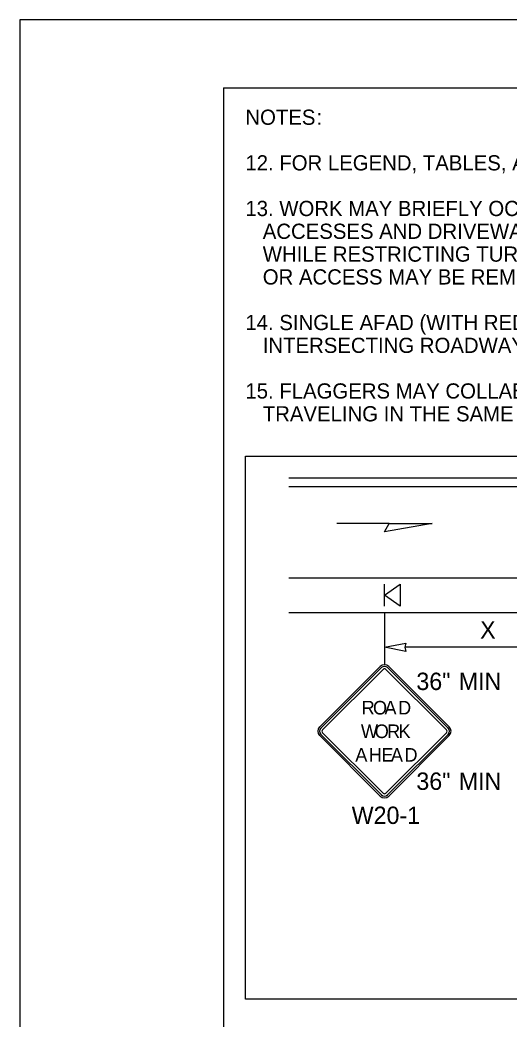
# Model space of a CAD drawing. Extents: x 99999.1 to 100095.7, y 99995 to 100010.7.
# Drawn here: x 100059.062 to 100061.313, y 100006.089 to 100010.687 of the extents above; entities that cross this region are included whole.
import ezdxf

# ---------------------------------------------------------------- set-up
doc = ezdxf.new("R2010")
doc.units = 0
for name, color, linetype in [('RD_ED_ShoulderPavedEdge', 7, 'Continuous'), ('RD_MK_LineDblYellowCenter', 7, 'Continuous'), ('RD_MK_LineEdgeWhite', 7, 'Continuous'), ('SH_GI_GeneralNotesBodyText', 7, 'Continuous'), ('SH_GI_PlotLimits', 7, 'Continuous'), ('SH_GI_SheetBorder', 7, 'Continuous'), ('TR_SN_ConstructionSigns', 7, 'Continuous'), ('TR_WZ_PortableSignMountBlk-Org', 7, 'Continuous'), ('TR_WZ_WorkZoneDetails', 7, 'Continuous'), ('TR_WZ_WorkZoneTextCurrent', 7, 'Continuous')]:
    doc.layers.add(name, color=color, linetype=linetype)

msp = doc.modelspace()

# ---------------------------------------------------------------- linework, layer by layer
at = {"layer": 'RD_ED_ShoulderPavedEdge'}
msp.add_line((100060.3, 100007.9602), (100064.9804, 100007.9602), dxfattribs=at)
at = {"layer": 'RD_MK_LineDblYellowCenter'}
for p, q in [((100060.3, 100008.5802), (100063.7402, 100008.5802)), ((100060.3, 100008.5402), (100063.7402, 100008.5402))]:
    msp.add_line(p, q, dxfattribs=at)
at = {"layer": 'RD_MK_LineEdgeWhite'}
msp.add_line((100060.3, 100008.1202), (100064.9804, 100008.1202), dxfattribs=at)
at = {"layer": 'SH_GI_PlotLimits'}
msp.add_lwpolyline([(100059.0625, 99999.6875), (100076.0625, 99999.6875), (100076.0625, 100010.6875), (100059.0625, 100010.6875)], close=True, dxfattribs=at)
at = {"layer": 'SH_GI_SheetBorder'}
for q in [(100060, 100000), (100075.75, 100010.375)]:
    msp.add_line((100060, 100010.375), q, dxfattribs=at)
at = {"layer": 'TR_SN_ConstructionSigns'}
for p, q in [((100060.7203, 100007.712), (100060.4419, 100007.4336)), ((100060.7258, 100007.7065), (100060.4474, 100007.428)), ((100060.4551, 100007.4203), (100060.7335, 100007.6987)), ((100060.7468, 100007.6987), (100061.0252, 100007.4203)), ((100061.0329, 100007.428), (100060.7545, 100007.7065)), ((100061.0385, 100007.4336), (100060.76, 100007.712)), ((100060.4474, 100007.3993), (100060.7258, 100007.1209)), ((100060.7335, 100007.1286), (100060.4551, 100007.4071)), ((100061.0252, 100007.4071), (100060.7468, 100007.1286)), ((100060.7545, 100007.1209), (100061.0329, 100007.3993)), ((100060.4419, 100007.3938), (100060.7203, 100007.1154)), ((100060.76, 100007.1154), (100061.0385, 100007.3938))]:
    msp.add_line(p, q, dxfattribs=at)
for centre, radius, start, end in [((100060.7402, 100007.6921), 0.0281, 45, 135), ((100060.7402, 100007.6921), 0.0203, 45, 135), ((100060.7402, 100007.6921), 0.00937, 45, 135), ((100060.4617, 100007.4137), 0.0281, 135, 225), ((100060.4617, 100007.4137), 0.0203, 135, 225), ((100060.4617, 100007.4137), 0.00937, 135, 225), ((100061.0186, 100007.4137), 0.00937, 315, 45), ((100061.0186, 100007.4137), 0.0203, 315, 45), ((100061.0186, 100007.4137), 0.0281, 315, 45), ((100060.7402, 100007.1353), 0.0203, 225, 315), ((100060.7402, 100007.1353), 0.00937, 225, 315), ((100060.7402, 100007.1353), 0.0281, 225, 315)]:
    msp.add_arc(centre, radius, start, end, dxfattribs=at)
at = {"layer": 'TR_WZ_PortableSignMountBlk-Org'}
msp.add_line((100060.7402, 100007.9902), (100060.7402, 100008.0902), dxfattribs=at)
msp.add_lwpolyline([(100060.7402, 100008.0401), (100060.812, 100008.0902), (100060.812, 100007.9902)], close=True, dxfattribs=at)
at = {"layer": 'TR_WZ_WorkZoneDetails'}
for p, q in [((100060.7624, 100008.3695), (100060.5213, 100008.3695)), ((100060.7402, 100007.9605), (100060.7402, 100007.7202)), ((100061.5964, 100007.8002), (100060.8339, 100007.8002))]:
    msp.add_line(p, q, dxfattribs=at)
for points in [[(100060.959, 100008.3695), (100060.7402, 100008.3309), (100060.7624, 100008.3695)], [(100060.7402, 100007.8002), (100060.8384, 100007.8195), (100060.8339, 100007.8002), (100060.8384, 100007.781)]]:
    msp.add_lwpolyline(points, close=True, dxfattribs=at)
at = {"layer": 'TR_WZ_WorkZoneTextCurrent'}
msp.add_lwpolyline([(100060.1, 100008.6802), (100065.15, 100008.6802), (100065.15, 100006.1804), (100060.1, 100006.1804)], close=True, dxfattribs=at)

# ---------------------------------------------------------------- texts
at = {"layer": 'SH_GI_GeneralNotesBodyText'}
for s, p in [('NOTES', (100060.1, 100010.205)), (':', (100060.4275, 100010.205)), ('12. FOR LEGEND, TABLES, AND ADDITIONAL NOTES: SEE TC430, SHEET 3.', (100060.1, 100009.995)), ('13. WORK MAY BRIEFLY OCCUR WITHIN LANE CLOSURE ACROSS INTERSECTING BUSINESS ', (100060.1, 100009.785)), ('ACCESSES AND DRIVEWAYS ONLY. ', (100060.18, 100009.68)), ('WHILE RESTRICTING TURNS FROM MAINLINE. CHANNELIZATION DEVICES DELINEATING APPROACH ', (100060.18, 100009.575)), ('OR ACCESS MAY BE REMOVED OR RELOCATED AS NEEDED.', (100060.18, 100009.47)), ('14. SINGLE AFAD (WITH RED FLAG/ RED GLOW CONE FLASHLIGHT) MAY BE ADDED TO THE ', (100060.1, 100009.26)), ('INTERSECTING ROADWAY APPROACH TO HELP GUIDE ALTERNATING & TURNING TRAFFIC.', (100060.18, 100009.155)), ('15. FLAGGERS MAY COLLABORATE TO RELEASE APPROACH/ACCESS AND MAINLINE TRAFFIC ', (100060.1, 100008.945)), ('TRAVELING IN THE SAME DIRECTION CONCURRENTLY.', (100060.18, 100008.84))]:
    msp.add_text(s, height=0.07, rotation=360, dxfattribs=at).set_placement(p)
at = {"layer": 'TR_SN_ConstructionSigns'}
for s, p in [('36"', (100060.8869, 100007.6035)), ('MIN', (100061.0819, 100007.6035)), ('36"', (100060.8869, 100007.1439)), ('MIN', (100061.0819, 100007.1439)), ('W20-1', (100060.5892, 100006.9871))]:
    msp.add_text(s, height=0.08, rotation=360, dxfattribs=at).set_placement(p)
for s, p in [('R', (100060.6351, 100007.491)), ('O', (100060.6872, 100007.491)), ('A', (100060.74, 100007.491)), ('D', (100060.8027, 100007.491)), ('W', (100060.6318, 100007.3824)), ('O', (100060.6951, 100007.3824)), ('R', (100060.7523, 100007.3824)), ('K', (100060.8047, 100007.3824)), ('A', (100060.6058, 100007.2739)), ('H', (100060.6683, 100007.2739)), ('E', (100060.7258, 100007.2739)), ('A', (100060.7695, 100007.2739)), ('D', (100060.832, 100007.2739))]:
    msp.add_text(s, height=0.0625, dxfattribs=at).set_placement(p)
at = {"layer": 'TR_WZ_WorkZoneTextCurrent'}
msp.add_text('X', height=0.08, rotation=360, dxfattribs=at).set_placement((100061.1804, 100007.8402))

doc.saveas('drawing.dxf')
